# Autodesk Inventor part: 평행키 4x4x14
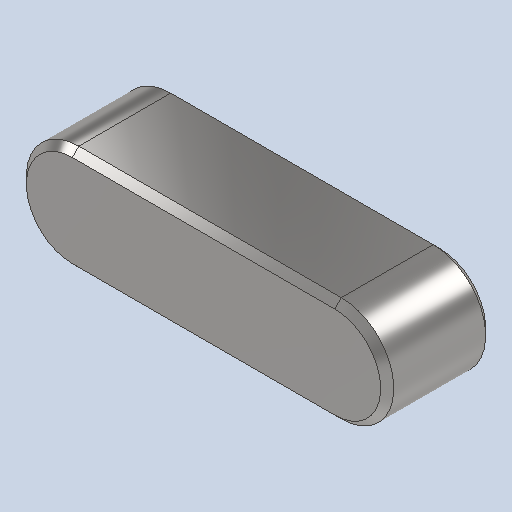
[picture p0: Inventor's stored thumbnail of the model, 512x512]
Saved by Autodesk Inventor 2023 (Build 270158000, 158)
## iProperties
Created: 2024-07
Part Number: 평행키 4x4x14
Material: 강철, 연강
Description: 키 및 해당 키홈
Document SubType Name: Modeling
Designer: home
Density: 7.85 g/cm^3
Appearance: 기본값
Author: jhkim
Sending System: Autodesk Inventor 2025
Preprocessor: ST-DEVELOPER v20
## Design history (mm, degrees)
feature "Solid1"
node "솔리드1"
